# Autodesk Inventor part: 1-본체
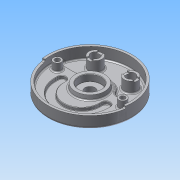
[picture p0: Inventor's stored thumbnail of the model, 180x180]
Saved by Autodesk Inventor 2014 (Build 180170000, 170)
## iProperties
Created: 2015-06
Part Number: 1-본체
Material: 알루미늄 6061
Document SubType Name: Modeling
Designer: Administrator
Density: 2.71 g/cm^3
Appearance: 알루미늄 - 평지
Mass: 1070.34 g
Surface Area: 1033.52 cm^2
Volume: 394.959 cm^3
Author: Administrator
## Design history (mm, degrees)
sketch "스케치1"
  geometry: C1 r 95 at (0, 0); 1 further point
  constraints: 1 centre point, 1 coincident
  dimensions: "d0" = 190 diameter of C1
extrude "돌출1" new body sketch "스케치1" distance "d1" = 32; taper "d2" = 0 deg
sketch "스케치2"
  geometry: L1 (-88.566, 16)-(-45.033, 16); L2 (45.033, 16)-(88.566, 16); C1 r 95 at (0, 0) reference; A1 r 90 centre (0, 0) between (-88.566, 16) and (88.566, 16); A2 r 42 centre (0, 0) between (36.373, 21) and (-36.373, 21); A3 r 10 centre (-45.033, 26) between (-45.033, 16) and (-36.373, 21); A4 r 10 centre (45.033, 26) between (36.373, 21) and (45.033, 16)
  constraints: 8 point on circle, 4 centre point, 4 end point, 4 tangent, 2 horizontal, 1 coincident, 1 collinear, 1 equal radius
  dimensions: "d3" = 180 diameter of A1; "d4" = 84 diameter of A2; "d6" = 16 distance from line of L2 C1.centre; "d7" = 10 radius of A4
extrude "돌출2" cut sketch "스케치2" distance "d8" = 25; taper "d9" = 0 deg
sketch "스케치3"
  geometry: L1 (-45.033, 16)-(-88.566, 16) reference; L2 (88.566, 16)-(45.033, 16) reference; C1 r 95 at (0, 0) reference; C2 r 90 at (0, 0); A1 r 10 centre (-45.033, 26) between (-45.033, 16) and (-36.373, 21) reference; A2 r 90 centre (0, 0) between (88.566, 16) and (-88.566, 16) reference; A3 r 10 centre (45.033, 26) between (36.373, 21) and (45.033, 16) reference; A4 r 42 centre (0, 0) between (36.373, 21) and (-36.373, 21) reference
  constraints: 1 centre point
  dimensions: "d10" = 180 diameter of C2
extrude "돌출3" cut sketch "스케치3" distance "d11" = 18; taper "d12" = 0 deg
sketch "스케치4"
  geometry: L1 (0, 0)-(-94.075, -13.221); L2 (0, 0)-(94.075, -13.221); C1 r 90 at (0, 0) reference; A1 r 95 centre (0, 0) between (-94.075, -13.221) and (94.075, -13.221) reference; 1 further point
  constraints: 4 end point, 3 point on circle, 2 horizontal alignment, 1 equal length
  dimensions: "d13" = 8 deg dimension on A1.centre L2.end point (95, 0)
extrude "돌출4" cut sketch "스케치4" distance "d14" = 5; taper "d15" = 0 deg
sketch "스케치5"
  geometry: L1 (45.033, 16)-(88.566, 16) reference; L2 (41, -19)-(41, -14); L3 (59, -19)-(59, -14); L4 (-41, -19)-(-41, -14); L5 (-59, -19)-(-59, -14); C1 r 35 at (0, 0); C2 r 9 at (-74, 0); C3 r 9 at (74, 0); A1 r 90 centre (0, 0) between (-88.566, 16) and (88.566, 16) reference; A2 r 42 centre (0, 0) between (36.373, 21) and (-36.373, 21) reference; A3 r 59 centre (0, -19) between (-59, -19) and (59, -19); A4 r 41 centre (0, -19) between (-41, -19) and (41, -19); A5 r 9 centre (-50, -14) between (-41, -14) and (-59, -14); A6 r 9 centre (50, -14) between (59, -14) and (41, -14); 2 further points
  constraints: 10 point on circle, 8 end point, 7 centre point, 6 parallel, 5 tangent, 3 vertical alignment, 2 equal radius, 2 horizontal alignment, 1 coincident, 1 perpendicular
  dimensions: "d16" = 70 diameter of C1; "d17" = 59 radius of A3; "d18" = 41 radius of A4; "d19" = 19 distance of A3.centre A1.centre; "d20" = 5 distance of L2.start L2.end; "d21" = 18 diameter of C2; "d22" = 148 distance of C3.centre C2.centre; "d23" = 74 distance of C1.centre C3.centre
extrude "돌출5" join sketch "스케치5" distance "d24" = 10; taper "d25" = -10 deg
extrude "돌출6" cut sketch "스케치5" distance "d26" = 7; taper "d27" = 0 deg
extrude "돌출7" join sketch "스케치5" stored distance "d28" = 7; taper "d29" = 0 deg
sketch "스케치6"
  geometry: C1 r 15 at (-40, 52); C2 r 15 at (40, 52); A1 r 95 centre (0, 0) between (94.075, -13.221) and (-94.075, -13.221) reference
  constraints: 2 centre point, 1 equal radius, 1 horizontal alignment
  dimensions: "d30" = 30 diameter of C1; "d31" = 80 distance of C2.centre C1.centre; "d32" = 40 horizontal distance of A1.centre C2.centre; "d33" = 52 vertical distance of A1.centre C2.centre
extrude "돌출8" join sketch "스케치6" stored distance "d34" = 7; taper "d35" = 0 deg
sketch "스케치7"
  geometry: L1 (-6, 21.657)-(6, 21.657); L2 (6, 21.657)-(6, -21.657); L3 (6, -21.657)-(-6, -21.657); L4 (-6, -21.657)-(-6, 21.657); L5 (58.343, 6)-(101.657, 6); L6 (101.657, 6)-(101.657, -6); L7 (101.657, -6)-(58.343, -6); L8 (58.343, -6)-(58.343, 6); C1 r 15 at (0, 0) reference; C2 r 15 at (80, 0) reference; 5 further points
  constraints: 16 end point, 4 midpoint, 4 parallel, 4 perpendicular, 2 horizontal, 2 horizontal alignment, 2 vertical alignment
  dimensions: "d36" = 12 distance of L1.start L1.end; "d38" = 43.31371 distance of L1.end L2.end
extrude "돌출9" cut sketch "스케치7" distance "d39" = 3; taper "d40" = 0 deg
sketch "스케치8"
  geometry: C1 r 15 at (-40, 52) reference; C2 r 15 at (40, 52) reference; 2 further points
  constraints: 2 coincident
hole "구멍1" sketch "스케치8" at (-40, 52), (40, 52) diameter "d41" = 20; stored, may be unused: countersink angle "d45" = 90 deg, drill point angle "d47" = 118 deg; dims "d42" = 6, "d43" = 4, "d44" = 2, "d46" = 8
sketch "스케치9"
  geometry: C1 r 9 at (-74, 0) reference; C2 r 9 at (74, 0) reference; 2 further points
  constraints: 2 coincident
hole "구멍2" sketch "스케치9" at (-74, 0), (74, 0) diameter "d48" = 11; stored, may be unused: countersink angle "d52" = 90 deg, drill point angle "d54" = 118 deg; dims "d49" = 6, "d50" = 18, "d51" = 11, "d53" = 8
sketch "스케치10"
  geometry: C1 r 95 at (0, 0) reference; C2 r 26 at (0, 0)
  constraints: 1 centre point, 1 coincident
  dimensions: "d55" = 52 diameter of C2
extrude "돌출10" join sketch "스케치10" distance "d56" = 12; taper "d57" = -15 deg
hole "구멍3" diameter "d60" = 23; stored, may be unused: countersink angle "d64" = 90 deg, drill point angle "d66" = 118 deg; dims "d58" = 10, "d59" = 10, "d61" = 6, "d62" = 50, "d63" = 15, "d65" = 8
sketch "스케치11"
  geometry: C1 r 95 at (0, 0) reference; C2 r 68 at (0, 0)
  constraints: 1 centre point, 1 coincident, 1 other
  dimensions: "d67" = 136 diameter of C2
feature "엠보싱1" sketch "스케치11" dims "d1" = 32, "d2" = 0, "d68" = 0.5, "d69" = 0
fillet "모깎기1" dims "d70" = 10
fillet "모깎기2" dims "d71" = 1
fillet "모깎기3" dims "d72" = 5
fillet "모깎기4" dims "d73" = 0.3
fillet "모깎기5" dims "d74" = 3
chamfer "모따기1" distance "d75" = 1; stored, may be unused: second distance "d76" = 2, angle "d77" = 45 deg
node "솔리드1"
other parameters: "d5" = 16
